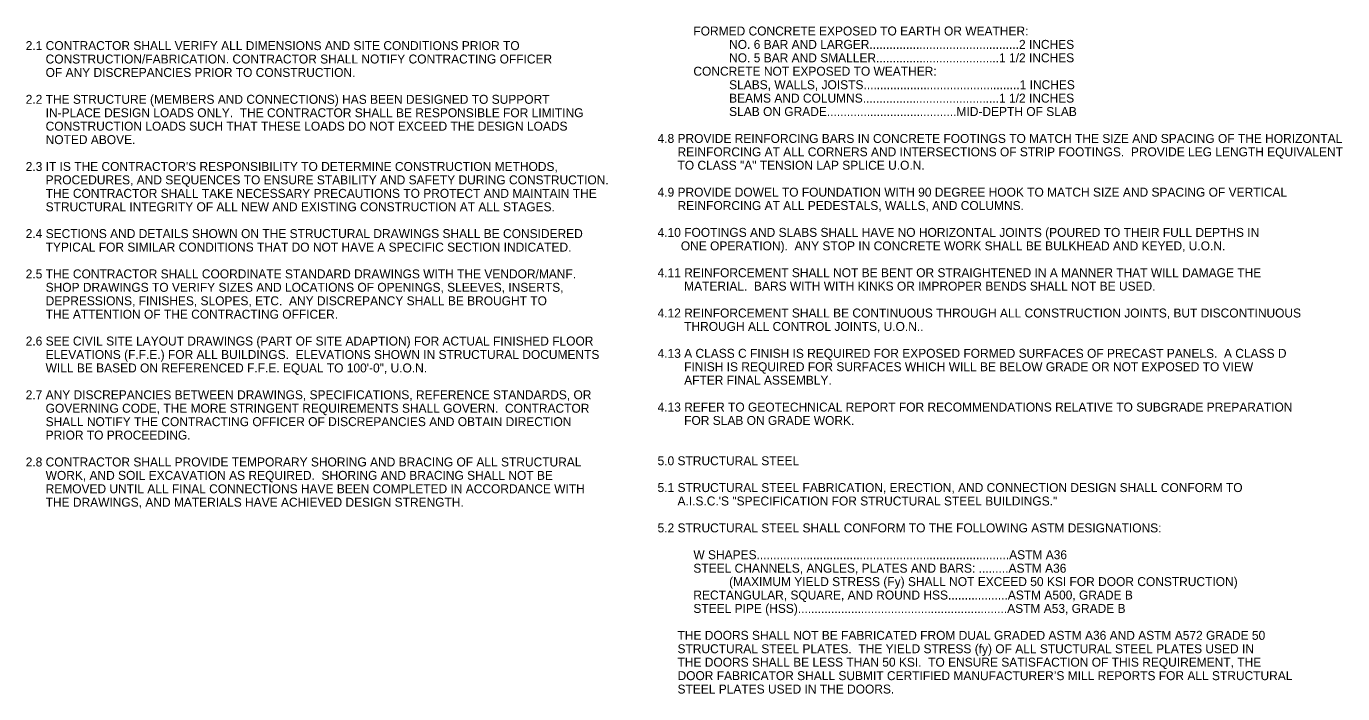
# Model space of a CAD drawing. Extents: x 0.17 to 2.69, y 0.12 to 1.72.
# Drawn here: x 0.174 to 1.707, y 0.141 to 0.918 of the extents above; entities that cross this region are included whole.
import ezdxf

# ---------------------------------------------------------------- set-up
doc = ezdxf.new("R2010")
doc.units = 0
doc.layers.add('G-ANNO-TEXT', color=7, linetype='Continuous')

msp = doc.modelspace()

# ---------------------------------------------------------------- texts
at = {"layer": 'G-ANNO-TEXT'}
for s, p in [('FORMED CONCRETE EXPOSED TO EARTH OR WEATHER:', (0.9507, 0.907)), ('2.1 CONTRACTOR SHALL VERIFY ALL DIMENSIONS AND SITE CONDITIONS PRIOR TO ', (0.1733, 0.89)), ('NO. 6 BAR AND LARGER.............................................2 INCHES', (0.9923, 0.8914)), ('      CONSTRUCTION/FABRICATION. CONTRACTOR SHALL NOTIFY CONTRACTING OFFICER', (0.1733, 0.8744)), ('NO. 5 BAR AND SMALLER.....................................1 1/2 INCHES', (0.9923, 0.8758)), ('      OF ANY DISCREPANCIES PRIOR TO CONSTRUCTION.', (0.1733, 0.8588)), ('CONCRETE NOT EXPOSED TO WEATHER:', (0.9507, 0.8602)), ('SLABS, WALLS, JOISTS...............................................1 INCHES', (0.9923, 0.8445)), ('2.2 THE STRUCTURE (MEMBERS AND CONNECTIONS) HAS BEEN DESIGNED TO SUPPORT', (0.1733, 0.8275)), ('BEAMS AND COLUMNS.........................................1 1/2 INCHES', (0.9923, 0.8289)), ('      IN-PLACE DESIGN LOADS ONLY.  THE CONTRACTOR SHALL BE RESPONSIBLE FOR LIMITING ', (0.1733, 0.8119)), ('SLAB ON GRADE.......................................MID-DEPTH OF SLAB', (0.9923, 0.8133)), ('      CONSTRUCTION LOADS SUCH THAT THESE LOADS DO NOT EXCEED THE DESIGN LOADS', (0.1733, 0.7963)), ('      NOTED ABOVE. ', (0.1733, 0.7806)), ('4.8 PROVIDE REINFORCING BARS IN CONCRETE FOOTINGS TO MATCH THE SIZE AND SPACING OF THE HORIZONTAL ', (0.909, 0.782)), ('      REINFORCING AT ALL CORNERS AND INTERSECTIONS OF STRIP FOOTINGS.  PROVIDE LEG LENGTH EQUIVALENT', (0.909, 0.7664)), ("2.3 IT IS THE CONTRACTOR'S RESPONSIBILITY TO DETERMINE CONSTRUCTION METHODS,", (0.1733, 0.7494)), ('      TO CLASS "A" TENSION LAP SPLICE U.O.N.', (0.909, 0.7508)), ('      PROCEDURES, AND SEQUENCES TO ENSURE STABILITY AND SAFETY DURING CONSTRUCTION.  ', (0.1733, 0.7338)), ('      THE CONTRACTOR SHALL TAKE NECESSARY PRECAUTIONS TO PROTECT AND MAINTAIN THE ', (0.1733, 0.7181)), ('4.9 PROVIDE DOWEL TO FOUNDATION WITH 90 DEGREE HOOK TO MATCH SIZE AND SPACING OF VERTICAL', (0.909, 0.7195)), ('      STRUCTURAL INTEGRITY OF ALL NEW AND EXISTING CONSTRUCTION AT ALL STAGES.  ', (0.1733, 0.7025)), ('      REINFORCING AT ALL PEDESTALS, WALLS, AND COLUMNS.', (0.909, 0.7039)), ('2.4 SECTIONS AND DETAILS SHOWN ON THE STRUCTURAL DRAWINGS SHALL BE CONSIDERED ', (0.1733, 0.6713)), ('4.10 FOOTINGS AND SLABS SHALL HAVE NO HORIZONTAL JOINTS (POURED TO THEIR FULL DEPTHS IN ', (0.909, 0.6727)), ('      TYPICAL FOR SIMILAR CONDITIONS THAT DO NOT HAVE A SPECIFIC SECTION INDICATED.  ', (0.1733, 0.6556)), ('       ONE OPERATION).  ANY STOP IN CONCRETE WORK SHALL BE BULKHEAD AND KEYED, U.O.N.', (0.909, 0.657)), ('2.5 THE CONTRACTOR SHALL COORDINATE STANDARD DRAWINGS WITH THE VENDOR/MANF.', (0.1733, 0.6244)), ('4.11 REINFORCEMENT SHALL NOT BE BENT OR STRAIGHTENED IN A MANNER THAT WILL DAMAGE THE', (0.909, 0.6258)), ('      SHOP DRAWINGS TO VERIFY SIZES AND LOCATIONS OF OPENINGS, SLEEVES, INSERTS,', (0.1733, 0.6088)), ('        MATERIAL.  BARS WITH WITH KINKS OR IMPROPER BENDS SHALL NOT BE USED.', (0.909, 0.6102)), ('      DEPRESSIONS, FINISHES, SLOPES, ETC.  ANY DISCREPANCY SHALL BE BROUGHT TO', (0.1733, 0.5931)), ('      THE ATTENTION OF THE CONTRACTING OFFICER.', (0.1733, 0.5775)), ('4.12 REINFORCEMENT SHALL BE CONTINUOUS THROUGH ALL CONSTRUCTION JOINTS, BUT DISCONTINUOUS', (0.909, 0.5789)), ('        THROUGH ALL CONTROL JOINTS, U.O.N..', (0.909, 0.5633)), ('2.6 SEE CIVIL SITE LAYOUT DRAWINGS (PART OF SITE ADAPTION) FOR ACTUAL FINISHED FLOOR  ', (0.1733, 0.5463)), ('      ELEVATIONS (F.F.E.) FOR ALL BUILDINGS.  ELEVATIONS SHOWN IN STRUCTURAL DOCUMENTS', (0.1733, 0.5306)), ('4.13 A CLASS C FINISH IS REQUIRED FOR EXPOSED FORMED SURFACES OF PRECAST PANELS.  A CLASS D ', (0.909, 0.532)), ('      WILL BE BASED ON REFERENCED F.F.E. EQUAL TO 100\'-0", U.O.N.', (0.1733, 0.515)), ('        FINISH IS REQUIRED FOR SURFACES WHICH WILL BE BELOW GRADE OR NOT EXPOSED TO VIEW ', (0.909, 0.5164)), ('        AFTER FINAL ASSEMBLY.', (0.909, 0.5008)), ('2.7 ANY DISCREPANCIES BETWEEN DRAWINGS, SPECIFICATIONS, REFERENCE STANDARDS, OR ', (0.1733, 0.4838)), ('      GOVERNING CODE, THE MORE STRINGENT REQUIREMENTS SHALL GOVERN.  CONTRACTOR ', (0.1733, 0.4681)), ('4.13 REFER TO GEOTECHNICAL REPORT FOR RECOMMENDATIONS RELATIVE TO SUBGRADE PREPARATION', (0.909, 0.4695)), ('      SHALL NOTIFY THE CONTRACTING OFFICER OF DISCREPANCIES AND OBTAIN DIRECTION ', (0.1733, 0.4525)), ('        FOR SLAB ON GRADE WORK.    ', (0.909, 0.4539)), ('      PRIOR TO PROCEEDING.         ', (0.1733, 0.4369)), ('2.8 CONTRACTOR SHALL PROVIDE TEMPORARY SHORING AND BRACING OF ALL STRUCTURAL ', (0.1733, 0.4056)), ('5.0 STRUCTURAL STEEL', (0.909, 0.407)), ('      WORK, AND SOIL EXCAVATION AS REQUIRED.  SHORING AND BRACING SHALL NOT BE ', (0.1733, 0.39)), ('      REMOVED UNTIL ALL FINAL CONNECTIONS HAVE BEEN COMPLETED IN ACCORDANCE WITH', (0.1733, 0.3744)), ('5.1 STRUCTURAL STEEL FABRICATION, ERECTION, AND CONNECTION DESIGN SHALL CONFORM TO ', (0.909, 0.3758)), ('      THE DRAWINGS, AND MATERIALS HAVE ACHIEVED DESIGN STRENGTH.', (0.1733, 0.3588)), ('      A.I.S.C.\'S "SPECIFICATION FOR STRUCTURAL STEEL BUILDINGS." ', (0.909, 0.3602)), ('5.2 STRUCTURAL STEEL SHALL CONFORM TO THE FOLLOWING ASTM DESIGNATIONS:', (0.909, 0.3289)), ('W SHAPES............................................................................ASTM A36', (0.9507, 0.2977)), ('STEEL CHANNELS, ANGLES, PLATES AND BARS: .........ASTM A36 ', (0.9507, 0.282)), ('(MAXIMUM YIELD STRESS (Fy) SHALL NOT EXCEED 50 KSI FOR DOOR CONSTRUCTION) ', (0.9923, 0.2664)), ('RECTANGULAR, SQUARE, AND ROUND HSS..................ASTM A500, GRADE B', (0.9507, 0.2508)), ('STEEL PIPE (HSS)...............................................................ASTM A53, GRADE B ', (0.9507, 0.2352)), ('      THE DOORS SHALL NOT BE FABRICATED FROM DUAL GRADED ASTM A36 AND ASTM A572 GRADE 50', (0.909, 0.2039)), ('      STRUCTURAL STEEL PLATES.  THE YIELD STRESS (fy) OF ALL STUCTURAL STEEL PLATES USED IN', (0.909, 0.1883)), ('      THE DOORS SHALL BE LESS THAN 50 KSI.  TO ENSURE SATISFACTION OF THIS REQUIREMENT, THE', (0.909, 0.1727)), ('      DOOR FABRICATOR SHALL SUBMIT CERTIFIED MANUFACTURER’S MILL REPORTS FOR ALL STRUCTURAL', (0.909, 0.157)), ('      STEEL PLATES USED IN THE DOORS.', (0.909, 0.1414))]:
    msp.add_text(s, height=0.010417, dxfattribs=at).set_placement(p)

doc.saveas('drawing.dxf')
